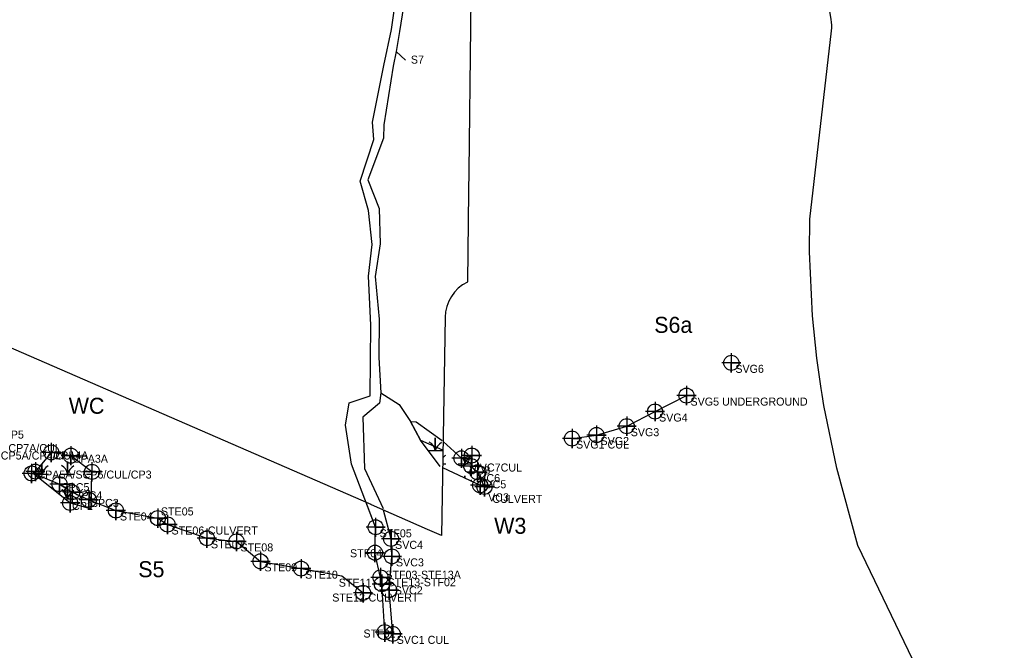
# Model space of a CAD drawing. Extents: x 1253697 to 1278588, y 912189 to 981699.
# Drawn here: x 1259443 to 1260665, y 914458 to 915246 of the extents above; entities that cross this region are included whole.
import ezdxf

# ---------------------------------------------------------------- set-up
doc = ezdxf.new("R2010")
doc.units = 0
for name, color, linetype in [('Default', 7, 'Continuous'), ('Exist Environmental Wetland Boundary', 7, 'Continuous'), ('Exist Environmental Wetland Boundary Cogo Comment', 7, 'Continuous'), ('Exist Environmental Wetland Boundary Cogo Number', 7, 'Continuous'), ('Exist Environmental Wetland Boundary Cogo Point CELL', 7, 'Continuous'), ('Exist Hydro Jurisdictional Stream or Body of Water Mitigable', 7, 'Continuous'), ('Exist Hydro Jurisdictional Stream or Body of Water Mitigable Cogo Comment', 7, 'Continuous'), ('Exist Hydro Jurisdictional Stream or Body of Water Mitigable Cogo Number', 7, 'Continuous'), ('Exist Hydro Jurisdictional Stream or Body of Water Mitigable Cogo Point CELL', 7, 'Continuous'), ('Exist Hydro Jurisdictional Stream or Body of Water NonMitigable', 7, 'Continuous'), ('Exist Hydro Jurisdictional Stream or Body of Water NonMitigable Cogo Comment', 7, 'Continuous'), ('Exist Hydro Jurisdictional Stream or Body of Water NonMitigable Cogo Number', 7, 'Continuous'), ('Exist Hydro Jurisdictional Stream or Body of Water NonMitigable Cogo Point CELL', 7, 'Continuous'), ('Exist Hydro Swamp or Marsh', 7, 'Continuous')]:
    doc.layers.add(name, color=color, linetype=linetype)

msp = doc.modelspace()

# ---------------------------------------------------------------- linework, layer by layer
at = {"layer": 'Default'}
for p, q in [((1260006.9, 915274.7), (1260006.4, 915236.1)), ((1260006.9, 915274.7), (1260006.4, 915236.1)), ((1260006.9, 915274.7), (1260006.4, 915236.1)), ((1260006.9, 915274.7), (1260006.4, 915236.1)), ((1260003.9, 915030.8), (1260002.5, 914918)), ((1260003.9, 915030.8), (1260002.5, 914918)), ((1260003.9, 915030.8), (1260002.5, 914918)), ((1260003.9, 915030.8), (1260002.5, 914918)), ((1259952.5, 914609.1), (1259882.5, 914640)), ((1259952.5, 914609.1), (1259882.5, 914640)), ((1259952.5, 914609.1), (1259882.5, 914640)), ((1259952.5, 914609.1), (1259882.5, 914640))]:
    msp.add_line(p, q, dxfattribs=at)
for points in [[(1260456.9, 915245.6), (1260380.3, 915705.7), (1260392.9, 916184.9), (1260575.8, 916412.4)], [(1260456.9, 915245.6), (1260380.3, 915705.7), (1260392.9, 916184.9), (1260575.8, 916412.4)], [(1260456.9, 915245.6), (1260380.3, 915705.7), (1260392.9, 916184.9), (1260575.8, 916412.4)], [(1260456.9, 915245.6), (1260380.3, 915705.7), (1260392.9, 916184.9), (1260575.8, 916412.4)], [(1260006.4, 915236.1), (1260004.3, 915056.4), (1260003.9, 915031)], [(1260006.4, 915236.1), (1260004.3, 915056.4), (1260003.9, 915031)], [(1260006.4, 915236.1), (1260004.3, 915056.4), (1260003.9, 915031)], [(1260006.4, 915236.1), (1260004.3, 915056.4), (1260003.9, 915031)], [(1261126.9, 913832.3), (1260885, 914025.7), (1260783.1, 914115.2), (1260719.8, 914184.5), (1260681.8, 914231.6), (1260621.8, 914315.9), (1260490.2, 914589.2), (1260463.9, 914685.8), (1260447.7, 914764), (1260445.4, 914777.7), (1260444.3, 914785.1), (1260438.9, 914823.1), (1260433.3, 914875.8), (1260429.6, 914955.5), (1260430.1, 914996.6), (1260457.3, 915231.6)], [(1261126.9, 913832.3), (1260885, 914025.7), (1260783.1, 914115.2), (1260719.8, 914184.5), (1260681.8, 914231.6), (1260621.8, 914315.9), (1260490.2, 914589.2), (1260463.9, 914685.8), (1260447.7, 914764), (1260445.4, 914777.7), (1260444.3, 914785.1), (1260438.9, 914823.1), (1260433.3, 914875.8), (1260429.6, 914955.5), (1260430.1, 914996.6), (1260457.3, 915231.6)], [(1261126.9, 913832.3), (1260885, 914025.7), (1260783.1, 914115.2), (1260719.8, 914184.5), (1260681.8, 914231.6), (1260621.8, 914315.9), (1260490.2, 914589.2), (1260463.9, 914685.8), (1260447.7, 914764), (1260445.4, 914777.7), (1260444.3, 914785.1), (1260438.9, 914823.1), (1260433.3, 914875.8), (1260429.6, 914955.5), (1260430.1, 914996.6), (1260457.3, 915231.6)], [(1261126.9, 913832.3), (1260885, 914025.7), (1260783.1, 914115.2), (1260719.8, 914184.5), (1260681.8, 914231.6), (1260621.8, 914315.9), (1260490.2, 914589.2), (1260463.9, 914685.8), (1260447.7, 914764), (1260445.4, 914777.7), (1260444.3, 914785.1), (1260438.9, 914823.1), (1260433.3, 914875.8), (1260429.6, 914955.5), (1260430.1, 914996.6), (1260457.3, 915231.6)], [(1259882.3, 914640.1), (1258730.7, 915140.3), (1258752.6, 915140.1), (1259232.8, 915134.8)], [(1259882.3, 914640.1), (1258730.7, 915140.3), (1258752.6, 915140.1), (1259232.8, 915134.8)], [(1259882.3, 914640.1), (1258730.7, 915140.3), (1258752.6, 915140.1), (1259232.8, 915134.8)], [(1259882.3, 914640.1), (1258730.7, 915140.3), (1258752.6, 915140.1), (1259232.8, 915134.8)], [(1259974.6, 914874), (1259969.9, 914601.5), (1259952.5, 914609.1)], [(1259974.6, 914874), (1259969.9, 914601.5), (1259952.5, 914609.1)], [(1259974.6, 914874), (1259969.9, 914601.5), (1259952.5, 914609.1)], [(1259974.6, 914874), (1259969.9, 914601.5), (1259952.5, 914609.1)]]:
    msp.add_lwpolyline(points, dxfattribs=at)
for centre, start, end in [((1260407.6, 915237.4), 353.4034, 9.4505), ((1260407.6, 915237.4), 353.4034, 9.4505), ((1260407.6, 915237.4), 353.4034, 9.4505), ((1260407.6, 915237.4), 353.4034, 9.4505), ((1260056.4, 915235.5), 179.2572, 179.3227), ((1260056.4, 915235.5), 179.2572, 179.3227), ((1260056.4, 915235.5), 179.2572, 179.3227), ((1260056.4, 915235.5), 179.2572, 179.3227), ((1260053.9, 915030.2), 179.1575, 179.3163), ((1260053.9, 915030.2), 179.1575, 179.3163), ((1260053.9, 915030.2), 179.1575, 179.3163), ((1260053.9, 915030.2), 179.1575, 179.3163), ((1260024.6, 914873.1), 116.2231, 179.0115), ((1260024.6, 914873.1), 116.2231, 179.0115), ((1260024.6, 914873.1), 116.2231, 179.0115), ((1260024.6, 914873.1), 116.2231, 179.0115), ((1259862.3, 914594.2), 66.2296, 66.5193), ((1259862.3, 914594.2), 66.2296, 66.5193), ((1259862.3, 914594.2), 66.2296, 66.5193), ((1259862.3, 914594.2), 66.2296, 66.5193), ((1259932.3, 914563.4), 66.2295, 66.2296), ((1259932.3, 914563.4), 66.2295, 66.2296)]:
    msp.add_arc(centre, 50, start, end, dxfattribs=at)
at = {"layer": 'Exist Environmental Wetland Boundary'}
for points in [[(1259968.4, 914687.8), (1259943.7, 914720.4), (1259931.4, 914743.9), (1259938.6, 914743.6), (1259971, 914720)], [(1259971.4, 914686.3), (1260018.3, 914664.2), (1260023.7, 914662.2), (1260015, 914680.5), (1260007.7, 914686.9), (1260007.9, 914701.4), (1259995, 914697.9), (1259972, 914719.1)], [(1259532.6, 914634.8), (1259533.5, 914681), (1259507.1, 914701.2), (1259482.7, 914705.3), (1259462.8, 914681.3), (1259459.9, 914679.5), (1259506.2, 914642.2), (1259532.6, 914634.8)]]:
    msp.add_lwpolyline(points, dxfattribs=at)
at = {"layer": 'Exist Environmental Wetland Boundary Cogo Point CELL'}
for points in [[(1259482.7, 914717.3), (1259482.7, 914693.3), (1259482.7, 914705.3), (1259494.7, 914705.3), (1259470.7, 914705.3)], [(1259507.1, 914713.2), (1259507.1, 914689.2), (1259507.1, 914701.2), (1259519.1, 914701.2), (1259495.1, 914701.2)], [(1259995, 914709.9), (1259995, 914685.9), (1259995, 914697.9), (1260007, 914697.9), (1259983, 914697.9)], [(1260007.9, 914713.4), (1260007.9, 914689.4), (1260007.9, 914701.4), (1260019.9, 914701.4), (1259995.9, 914701.4)], [(1259462.8, 914693.3), (1259462.8, 914669.3), (1259462.8, 914681.3), (1259474.8, 914681.3), (1259450.8, 914681.3)], [(1259533.5, 914693), (1259533.5, 914669), (1259533.5, 914681), (1259545.5, 914681), (1259521.5, 914681)], [(1260007.3, 914700.2), (1260007.3, 914676.2), (1260007.3, 914688.2), (1260019.3, 914688.2), (1259995.3, 914688.2)], [(1260015, 914692.5), (1260015, 914668.5), (1260015, 914680.5), (1260027, 914680.5), (1260003, 914680.5)], [(1260018.3, 914676.2), (1260018.3, 914652.2), (1260018.3, 914664.2), (1260030.3, 914664.2), (1260006.3, 914664.2)], [(1260023.7, 914674.2), (1260023.7, 914650.2), (1260023.7, 914662.2), (1260035.7, 914662.2), (1260011.7, 914662.2)], [(1259506.2, 914654.2), (1259506.2, 914630.2), (1259506.2, 914642.2), (1259518.2, 914642.2), (1259494.2, 914642.2)]]:
    msp.add_lwpolyline(points, dxfattribs=at)
for centre in [(1259482.7, 914705.3), (1259507.1, 914701.2), (1259995, 914697.9), (1260007.9, 914701.4), (1259462.8, 914681.3), (1259533.5, 914681), (1260007.3, 914688.2), (1260015, 914680.5), (1260018.3, 914664.2), (1260023.7, 914662.2), (1259506.2, 914642.2)]:
    msp.add_circle(centre, 9.38, dxfattribs=at)
at = {"layer": 'Exist Hydro Jurisdictional Stream or Body of Water Mitigable'}
msp.add_line((1259913.5, 915205.6), (1259925.3, 915194.9), dxfattribs=at)
for points in [[(1259898, 915188.1), (1259907.7, 915233.3), (1259913.9, 915277.1), (1259902.3, 915349.2), (1259891.4, 915397.9), (1259892.3, 915438.6), (1259892.2, 915494.9), (1259895.3, 915520.1), (1259898.5, 915553.2), (1259896.3, 915606), (1259889.6, 915652.5), (1259879.6, 915693.1), (1259870.5, 915716.9), (1259848.7, 915732.4), (1259842.7, 915753.3)], [(1259858.1, 915763.3), (1259866.4, 915747.4), (1259881.4, 915727.8), (1259893.1, 915700.3), (1259903.1, 915661.5), (1259907.6, 915609), (1259909.9, 915556.8), (1259902.8, 915499.7), (1259901, 915442.3), (1259899.6, 915402.4), (1259911.8, 915346.2), (1259925.7, 915280.6), (1259917.8, 915230.7), (1259913.5, 915205.6), (1259909.7, 915187.3), (1259897.9, 915114.3), (1259897.5, 915097.5), (1259878, 915045.5), (1259892.1, 915009.8)], [(1259887.8, 914611.8), (1259857.6, 914690.6), (1259850.1, 914739.4), (1259854.6, 914767.2), (1259881, 914776.1), (1259881.9, 914864.1), (1259879, 914925.1), (1259883.4, 914964.8), (1259879.1, 915007.3), (1259868.6, 915043.9), (1259885.4, 915095.7), (1259884.1, 915117.5), (1259898, 915188.1)], [(1259909.7, 915187.3), (1259897.9, 915114.3), (1259897.5, 915097.5), (1259878, 915045.5), (1259892.1, 915009.8), (1259893.6, 914965.7), (1259887.2, 914924.9), (1259892.2, 914871.6), (1259892, 914823.7), (1259894.2, 914779.8), (1259892.6, 914766.8), (1259871.7, 914749.3), (1259874.1, 914685.1), (1259897.3, 914635.3)], [(1259894.2, 914779.8), (1259917.1, 914764.9), (1259931.4, 914743.9), (1259943.7, 914720.4), (1259971.2, 914708.7)], [(1259459.9, 914679.5), (1259492.9, 914665.7), (1259508.9, 914655.5), (1259529.6, 914646), (1259563.4, 914632.8), (1259615.7, 914623.3), (1259627.9, 914615.3), (1259677.1, 914598.1), (1259714, 914594.2), (1259743.9, 914569.3), (1259794.7, 914560.2), (1259845.4, 914551.1), (1259872.1, 914530.1)], [(1259899.1, 914480.9), (1259895.6, 914540.9), (1259893.9, 914549.3), (1259887, 914580.1), (1259887.8, 914611.8), (1259875.9, 914642.8)], [(1259909.1, 914478.8), (1259904.8, 914533.4), (1259908.2, 914575.5), (1259907.1, 914597.4), (1259897.8, 914633.2)]]:
    msp.add_lwpolyline(points, dxfattribs=at)
at = {"layer": 'Exist Hydro Jurisdictional Stream or Body of Water Mitigable Cogo Point CELL'}
for points in [[(1259458.1, 914691), (1259458.1, 914667), (1259458.1, 914679), (1259470.1, 914679), (1259446.1, 914679)], [(1259492.9, 914677.7), (1259492.9, 914653.7), (1259492.9, 914665.7), (1259504.9, 914665.7), (1259480.9, 914665.7)], [(1259508.9, 914667.5), (1259508.9, 914643.5), (1259508.9, 914655.5), (1259520.9, 914655.5), (1259496.9, 914655.5)], [(1259529.6, 914658), (1259529.6, 914634), (1259529.6, 914646), (1259541.6, 914646), (1259517.6, 914646)], [(1259563.4, 914644.8), (1259563.4, 914620.8), (1259563.4, 914632.8), (1259575.4, 914632.8), (1259551.4, 914632.8)], [(1259615.7, 914635.3), (1259615.7, 914611.3), (1259615.7, 914623.3), (1259627.7, 914623.3), (1259603.7, 914623.3)], [(1259627.9, 914627.3), (1259627.9, 914603.3), (1259627.9, 914615.3), (1259639.9, 914615.3), (1259615.9, 914615.3)], [(1259887.8, 914623.8), (1259887.8, 914599.8), (1259887.8, 914611.8), (1259899.8, 914611.8), (1259875.8, 914611.8)], [(1259887.8, 914623.8), (1259887.8, 914599.8), (1259887.8, 914611.8), (1259899.8, 914611.8), (1259875.8, 914611.8)], [(1259677.1, 914610.1), (1259677.1, 914586.1), (1259677.1, 914598.1), (1259689.1, 914598.1), (1259665.1, 914598.1)], [(1259714, 914606.2), (1259714, 914582.2), (1259714, 914594.2), (1259726, 914594.2), (1259702, 914594.2)], [(1259907.1, 914609.4), (1259907.1, 914585.4), (1259907.1, 914597.4), (1259919.1, 914597.4), (1259895.1, 914597.4)], [(1259907.1, 914609.4), (1259907.1, 914585.4), (1259907.1, 914597.4), (1259919.1, 914597.4), (1259895.1, 914597.4)], [(1259887, 914592.1), (1259887, 914568.1), (1259887, 914580.1), (1259899, 914580.1), (1259875, 914580.1)], [(1259887, 914592.1), (1259887, 914568.1), (1259887, 914580.1), (1259899, 914580.1), (1259875, 914580.1)], [(1259743.9, 914581.3), (1259743.9, 914557.3), (1259743.9, 914569.3), (1259755.9, 914569.3), (1259731.9, 914569.3)], [(1259908.2, 914587.5), (1259908.2, 914563.5), (1259908.2, 914575.5), (1259920.2, 914575.5), (1259896.2, 914575.5)], [(1259908.2, 914587.5), (1259908.2, 914563.5), (1259908.2, 914575.5), (1259920.2, 914575.5), (1259896.2, 914575.5)], [(1259794.7, 914572.2), (1259794.7, 914548.2), (1259794.7, 914560.2), (1259806.7, 914560.2), (1259782.7, 914560.2)], [(1259893.9, 914561.3), (1259893.9, 914537.3), (1259893.9, 914549.3), (1259905.9, 914549.3), (1259881.9, 914549.3)], [(1259893.9, 914561.3), (1259893.9, 914537.3), (1259893.9, 914549.3), (1259905.9, 914549.3), (1259881.9, 914549.3)], [(1259895.6, 914552.9), (1259895.6, 914528.9), (1259895.6, 914540.9), (1259907.6, 914540.9), (1259883.6, 914540.9)], [(1259895.6, 914552.9), (1259895.6, 914528.9), (1259895.6, 914540.9), (1259907.6, 914540.9), (1259883.6, 914540.9)], [(1259904.8, 914545.4), (1259904.8, 914521.4), (1259904.8, 914533.4), (1259916.8, 914533.4), (1259892.8, 914533.4)], [(1259904.8, 914545.4), (1259904.8, 914521.4), (1259904.8, 914533.4), (1259916.8, 914533.4), (1259892.8, 914533.4)], [(1259872.1, 914542.1), (1259872.1, 914518.1), (1259872.1, 914530.1), (1259884.1, 914530.1), (1259860.1, 914530.1)], [(1259899.1, 914492.9), (1259899.1, 914468.9), (1259899.1, 914480.9), (1259911.1, 914480.9), (1259887.1, 914480.9)], [(1259899.1, 914492.9), (1259899.1, 914468.9), (1259899.1, 914480.9), (1259911.1, 914480.9), (1259887.1, 914480.9)], [(1259909.1, 914490.8), (1259909.1, 914466.8), (1259909.1, 914478.8), (1259921.1, 914478.8), (1259897.1, 914478.8)], [(1259909.1, 914490.8), (1259909.1, 914466.8), (1259909.1, 914478.8), (1259921.1, 914478.8), (1259897.1, 914478.8)]]:
    msp.add_lwpolyline(points, dxfattribs=at)
for centre in [(1259458.1, 914679), (1259492.9, 914665.7), (1259508.9, 914655.5), (1259529.6, 914646), (1259563.4, 914632.8), (1259615.7, 914623.3), (1259627.9, 914615.3), (1259887.8, 914611.8), (1259887.8, 914611.8), (1259677.1, 914598.1), (1259907.1, 914597.4), (1259907.1, 914597.4), (1259714, 914594.2), (1259887, 914580.1), (1259887, 914580.1), (1259908.2, 914575.5), (1259908.2, 914575.5), (1259743.9, 914569.3), (1259794.7, 914560.2), (1259893.9, 914549.3), (1259893.9, 914549.3), (1259895.6, 914540.9), (1259895.6, 914540.9), (1259904.8, 914533.4), (1259904.8, 914533.4), (1259872.1, 914530.1), (1259899.1, 914480.9), (1259899.1, 914480.9), (1259909.1, 914478.8), (1259909.1, 914478.8)]:
    msp.add_circle(centre, 9.38, dxfattribs=at)
at = {"layer": 'Exist Hydro Jurisdictional Stream or Body of Water NonMitigable'}
msp.add_lwpolyline([(1260133.1, 914722.6), (1260163.7, 914727), (1260201.4, 914738), (1260236.8, 914756.3), (1260276.1, 914776.2)], dxfattribs=at)
at = {"layer": 'Exist Hydro Jurisdictional Stream or Body of Water NonMitigable Cogo Point CELL'}
for points in [[(1260332.1, 914829.1), (1260332.1, 914805.1), (1260332.1, 914817.1), (1260344.1, 914817.1), (1260320.1, 914817.1)], [(1260276.1, 914788.2), (1260276.1, 914764.2), (1260276.1, 914776.2), (1260288.1, 914776.2), (1260264.1, 914776.2)], [(1260236.8, 914768.3), (1260236.8, 914744.3), (1260236.8, 914756.3), (1260248.8, 914756.3), (1260224.8, 914756.3)], [(1260163.7, 914739), (1260163.7, 914715), (1260163.7, 914727), (1260175.7, 914727), (1260151.7, 914727)], [(1260201.4, 914750), (1260201.4, 914726), (1260201.4, 914738), (1260213.4, 914738), (1260189.4, 914738)], [(1260133.1, 914734.6), (1260133.1, 914710.6), (1260133.1, 914722.6), (1260145.1, 914722.6), (1260121.1, 914722.6)]]:
    msp.add_lwpolyline(points, dxfattribs=at)
for centre in [(1260332.1, 914817.1), (1260276.1, 914776.2), (1260236.8, 914756.3), (1260201.4, 914738), (1260133.1, 914722.6), (1260163.7, 914727)]:
    msp.add_circle(centre, 9.38, dxfattribs=at)
at = {"layer": 'Exist Hydro Swamp or Marsh'}
for p, q in [((1259962.2, 914714.6), (1259962.2, 914714.6)), ((1259971.5, 914691.2), (1259975.7, 914691.2)), ((1259526.5, 914678.3), (1259533.4, 914678.3)), ((1259526.5, 914647.5), (1259532.8, 914647.5))]:
    msp.add_line(p, q, dxfattribs=at)
for points in [[(1259953.6, 914707.5), (1259962.2, 914707.5), (1259962.2, 914723.3), (1259962.2, 914707.5), (1259970.8, 914707.5)], [(1259462.1, 914678.3), (1259470.7, 914678.3), (1259470.7, 914690.8)], [(1259470.7, 914690.8), (1259470.7, 914678.3), (1259479.3, 914678.3)], [(1259494.3, 914678.3), (1259502.9, 914678.3), (1259502.9, 914694.1), (1259502.9, 914678.3), (1259511.5, 914678.3)], [(1259990.7, 914691.2), (1259999.3, 914691.2), (1259999.3, 914699.1)], [(1259999.3, 914699.1), (1259999.3, 914691.2), (1260007.7, 914691.2)], [(1259999.3, 914673.1), (1259999.3, 914676.2), (1259999.3, 914673.1)], [(1259499.6, 914647.5), (1259502.9, 914647.5), (1259502.9, 914663.3), (1259502.9, 914647.5), (1259511.5, 914647.5)]]:
    msp.add_lwpolyline(points, dxfattribs=at)
for centre, radius, start, end in [((1259949.9, 914706.6), 12.3, 4.1403, 67.535), ((1259980.4, 914701.4), 19.2, 122.1274, 161.6222), ((1259985.4, 914685.2), 19.2, 122.1274, 135.8056), ((1259987.1, 914690.3), 12.3, 4.1403, 40.2113), ((1260017.6, 914685.2), 19.2, 123.576, 161.6222), ((1259458.4, 914677.4), 12.3, 4.1403, 46.2706), ((1259488.9, 914672.2), 19.2, 122.1274, 161.6222), ((1259490.6, 914677.4), 12.3, 4.1403, 67.535), ((1259521.1, 914672.2), 19.2, 122.1274, 161.6222), ((1260017.6, 914654.4), 19.2, 122.1274, 126.2033), ((1259490.6, 914646.6), 12.3, 4.1403, 67.535), ((1259521.1, 914641.5), 19.2, 122.1274, 161.6222), ((1259522.8, 914646.6), 12.3, 34.4087, 67.535)]:
    msp.add_arc(centre, radius, start, end, dxfattribs=at)

# ---------------------------------------------------------------- texts
at = {"layer": 'Exist Environmental Wetland Boundary Cogo Comment'}
for s, p in [('CP7A/CUL', (1259429.1, 914705.7)), ('CP5A/CP4/CUL', (1259419.6, 914696.4)), ('CPA4A', (1259485.2, 914696.6)), ('CPA3A', (1259509.6, 914692.4)), ('VC7CUL', (1260017.9, 914681.4)), ('CPA5A/SCP6/CUL/CP3', (1259465.3, 914672.6)), ('VC8', (1260005, 914677.9)), ('VC6', (1260017.3, 914668.2)), ('VC5', (1260025, 914660.5)), ('VC3', (1260028.3, 914644.2)), ('CP2', (1259508.7, 914633.5)), ('CULVERT', (1260033.7, 914642.2))]:
    msp.add_text(s, height=10, dxfattribs=at).set_placement(p)
at = {"layer": 'Exist Environmental Wetland Boundary Cogo Number'}
for s, p in [('WC', (1259504.5, 914753.5)), ('W3', (1260035.9, 914603.7))]:
    msp.add_text(s, height=20, dxfattribs=at).set_placement(p)
at = {"layer": 'Exist Hydro Jurisdictional Stream or Body of Water Mitigable'}
msp.add_text('S7', height=10, dxfattribs=at).set_placement((1259931.8, 915190.6))
at = {"layer": 'Exist Hydro Jurisdictional Stream or Body of Water Mitigable Cogo Comment'}
for s, p in [('SPC8/CP5', (1259383.8, 914722.5)), ('SPC5', (1259495.4, 914656.9)), ('SPC4', (1259511.4, 914646.8)), ('SPC3', (1259532.1, 914637.2)), ('STE04', (1259568.4, 914620.3)), ('STE05', (1259619.6, 914626.6)), ('STE06-CULVERT', (1259632.9, 914602.8)), ('STF05', (1259892.8, 914599.3)), ('STE07', (1259682.1, 914585.6)), ('STE08', (1259719, 914581.7)), ('SVC4', (1259912.1, 914584.9)), ('STF04', (1259855.8, 914574.4)), ('SVC3', (1259913.2, 914563)), ('STE09', (1259748.9, 914556.8)), ('STE10', (1259799.7, 914547.7)), ('STF03-STE13A', (1259899.9, 914547.6)), ('STE11', (1259841.8, 914537.6)), ('STE13-STF02', (1259902.6, 914538.2)), ('SVC2', (1259911.7, 914528.1)), ('STE12-CULVERT', (1259833.6, 914519.1)), ('STF01', (1259872.6, 914474.2)), ('SVC1 CUL', (1259914.1, 914466.3))]:
    msp.add_text(s, height=10, dxfattribs=at).set_placement(p)
at = {"layer": 'Exist Hydro Jurisdictional Stream or Body of Water Mitigable Cogo Number'}
msp.add_text('S5', height=20, dxfattribs=at).set_placement((1259591.3, 914549.5))
at = {"layer": 'Exist Hydro Jurisdictional Stream or Body of Water NonMitigable Cogo Comment'}
for s, p in [('SVG6', (1260337.1, 914804.6)), ('SVG5 UNDERGROUND', (1260281.1, 914763.7)), ('SVG4', (1260241.8, 914743.8)), ('SVG3', (1260206.4, 914725.5)), ('SVG1 CUL', (1260138.1, 914710.1)), ('SVG2', (1260168.7, 914714.5))]:
    msp.add_text(s, height=10, dxfattribs=at).set_placement(p)
at = {"layer": 'Exist Hydro Jurisdictional Stream or Body of Water NonMitigable Cogo Number'}
msp.add_text('S6a', height=20, dxfattribs=at).set_placement((1260235.8, 914854.5))

doc.saveas('drawing.dxf')
